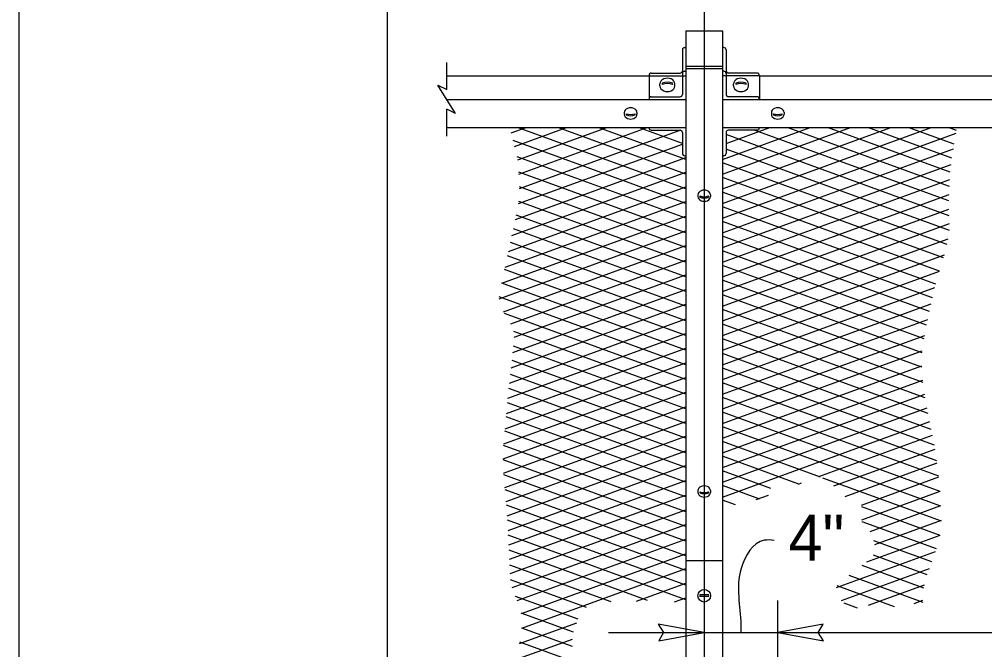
# Model space of a CAD drawing. Extents: x 0 to 2.83, y -0.03 to 1.83.
# Drawn here: x 0 to 0.2734, y 1.5079 to 1.6864 of the extents above; entities that cross this region are included whole.
import ezdxf

# ---------------------------------------------------------------- set-up
doc = ezdxf.new("R2010")
doc.units = 0
for name, color, linetype in [('52', 7, 'Continuous'), ('54', 7, 'Continuous'), ('55', 7, 'Continuous'), ('56', 7, 'Continuous'), ('57', 7, 'Continuous'), ('63', 7, 'Continuous')]:
    doc.layers.add(name, color=color, linetype=linetype)

msp = doc.modelspace()

# ---------------------------------------------------------------- linework, layer by layer
at = {"layer": '52'}
for p, q in [((0.18878094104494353, 1.6831667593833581), (0.19919760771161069, 1.6831667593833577)), ((0.18878094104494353, 1.6831667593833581), (0.18878094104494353, 1.6707794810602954)), ((0.1991976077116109, 1.6831667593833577), (0.19919760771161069, 1.6707794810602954)), ((0.18780437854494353, 1.6777778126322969), (0.18780437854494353, 1.665152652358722)), ((0.1884554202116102, 1.6784288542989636), (0.18878094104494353, 1.6784288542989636)), ((0.199523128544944, 1.6784288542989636), (0.19919760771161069, 1.6784288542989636)), ((0.20017417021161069, 1.6777778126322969), (0.20017417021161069, 1.665152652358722)), ((0.17901531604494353, 1.6711973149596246), (0.1871533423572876, 1.6711973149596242)), ((0.1884554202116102, 1.6717331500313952), (0.18878094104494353, 1.6717331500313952)), ((0.18878094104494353, 1.6731232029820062), (0.1991976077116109, 1.6731232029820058)), ((0.19919760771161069, 1.6723751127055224), (0.18878094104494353, 1.6723751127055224)), ((0.18878094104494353, 1.6707794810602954), (0.18878094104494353, 1.5329433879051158)), ((0.199523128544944, 1.6717331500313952), (0.19919760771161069, 1.6717331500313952)), ((0.19919760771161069, 1.6707794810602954), (0.19919760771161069, 1.5329433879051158)), ((0.20896323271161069, 1.6711973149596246), (0.20082520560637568, 1.6711973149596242)), ((0.1210726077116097, 1.670449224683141), (0.17836427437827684, 1.670449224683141)), ((0.17836427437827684, 1.670546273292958), (0.17836427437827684, 1.6637535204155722)), ((0.17836427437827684, 1.670449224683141), (0.18878094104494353, 1.670449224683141)), ((0.18145672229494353, 1.6675598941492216), (0.18145672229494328, 1.6681390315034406)), ((0.18568849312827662, 1.6675598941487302), (0.18568849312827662, 1.6681390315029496)), ((0.20961427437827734, 1.670449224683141), (0.19919760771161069, 1.670449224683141)), ((0.20229005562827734, 1.6675598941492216), (0.2022900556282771, 1.6681390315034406)), ((0.20652182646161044, 1.6675598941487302), (0.20652182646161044, 1.6681390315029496)), ((0.20961427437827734, 1.670546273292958), (0.20961427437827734, 1.6637535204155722)), ((0.2096142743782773, 1.670449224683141), (0.6054476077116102, 1.670449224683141)), ((0.1210726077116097, 1.6637535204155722), (0.18878094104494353, 1.6637535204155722)), ((0.17901531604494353, 1.6645016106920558), (0.18715333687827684, 1.6645016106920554)), ((0.1991976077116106, 1.6637535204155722), (0.6054476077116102, 1.6637535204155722)), ((0.20896323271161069, 1.6645016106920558), (0.20082521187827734, 1.6645016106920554)), ((0.17136557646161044, 1.6600087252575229), (0.1713655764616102, 1.659518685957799)), ((0.17494630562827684, 1.660008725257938), (0.17494630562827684, 1.6595186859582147)), ((0.21303224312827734, 1.660008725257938), (0.21303224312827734, 1.6595186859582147)), ((0.21661297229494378, 1.6600087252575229), (0.216612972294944, 1.659518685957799)), ((0.1210726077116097, 1.6557738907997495), (0.18878094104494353, 1.6557738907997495)), ((0.17836427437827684, 1.6557628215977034), (0.17836427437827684, 1.6556768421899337)), ((0.17901531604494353, 1.655025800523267), (0.18715333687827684, 1.655025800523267)), ((0.18780437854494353, 1.6543747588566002), (0.18780437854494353, 1.6484453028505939)), ((0.1991976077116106, 1.6557738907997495), (0.6054476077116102, 1.6557738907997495)), ((0.20017417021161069, 1.6543747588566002), (0.20017417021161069, 1.6484453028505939)), ((0.20896323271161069, 1.655025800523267), (0.20082521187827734, 1.655025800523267)), ((0.20961427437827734, 1.6557628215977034), (0.20961427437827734, 1.6556768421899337)), ((0.1884554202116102, 1.6477942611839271), (0.18878094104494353, 1.6477942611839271)), ((0.199523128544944, 1.6477942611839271), (0.19919760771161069, 1.6477942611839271)), ((0.19219890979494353, 1.636711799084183), (0.19219890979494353, 1.6362217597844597)), ((0.19577963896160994, 1.6367117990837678), (0.1957796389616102, 1.636221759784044)), ((0.19219890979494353, 1.552925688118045), (0.19219890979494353, 1.552435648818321)), ((0.19577963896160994, 1.5529256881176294), (0.1957796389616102, 1.552435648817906)), ((0.18878094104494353, 1.5330983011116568), (0.19919760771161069, 1.5330983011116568)), ((0.18878094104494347, 1.5329433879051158), (0.18878094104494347, 1.1621577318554)), ((0.1991976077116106, 1.5329433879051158), (0.1991976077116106, 1.1621577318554)), ((0.19523631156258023, 1.5233909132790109), (0.19274223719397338, 1.5233909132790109)), ((0.19523631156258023, 1.5229297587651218), (0.19274223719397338, 1.5229297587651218))]:
    msp.add_line(p, q, dxfattribs=at)
msp.add_circle((0.1939892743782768, 1.5231603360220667), 0.0017903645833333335, dxfattribs=at)
for centre, radius, start, end in [((0.1884554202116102, 1.6777778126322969), 0.0006510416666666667, 90, 180), ((0.199523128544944, 1.6777778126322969), 0.0006510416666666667, 7.0164775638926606e-15, 90), ((0.17901531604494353, 1.670546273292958), 0.0006510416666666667, 90.00000000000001, 188.57284229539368), ((0.18715333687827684, 1.6718483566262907), 0.0006510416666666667, 270, 0), ((0.1884554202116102, 1.6710821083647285), 0.0006510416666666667, 90, 180), ((0.199523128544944, 1.6710821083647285), 0.0006510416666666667, 7.0164775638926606e-15, 90), ((0.20082521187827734, 1.6718483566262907), 0.0006510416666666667, 180, 270), ((0.20896323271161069, 1.670546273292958), 0.0006510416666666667, 351.4271577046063, 90), ((0.18357260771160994, 1.6645999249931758), 0.004024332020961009, 68.51761783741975, 111.48238216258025), ((0.18357260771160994, 1.66418861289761), 0.004024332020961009, 68.51761783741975, 111.48238216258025), ((0.20440594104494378, 1.6645999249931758), 0.004024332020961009, 68.51761783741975, 111.48238216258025), ((0.20440594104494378, 1.66418861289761), 0.004024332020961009, 68.51761783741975, 111.48238216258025), ((0.17901531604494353, 1.663850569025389), 0.0006510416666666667, 90.00000000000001, 188.57284229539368), ((0.18715333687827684, 1.665152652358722), 0.0006510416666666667, 270, 0), ((0.20082521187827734, 1.665152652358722), 0.0006510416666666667, 180, 270), ((0.20896323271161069, 1.663850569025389), 0.0006510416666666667, 351.4271577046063, 90), ((0.17315594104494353, 1.66286134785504), 0.003405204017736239, 248.51761783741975, 291.4823821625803), ((0.17315594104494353, 1.6625133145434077), 0.003405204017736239, 248.51761783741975, 291.4823821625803), ((0.21482260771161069, 1.66286134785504), 0.003405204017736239, 248.51761783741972, 291.4823821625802), ((0.21482260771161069, 1.6625133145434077), 0.003405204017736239, 248.51761783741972, 291.4823821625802), ((0.17901531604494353, 1.6556768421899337), 0.0006510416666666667, 171.42715770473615, 270), ((0.18715333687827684, 1.6543747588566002), 0.0006510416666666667, 0, 89.99999999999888), ((0.20082521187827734, 1.6543747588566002), 0.0006510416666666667, 90.00000000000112, 180), ((0.20896323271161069, 1.6556768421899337), 0.0006510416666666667, 270, 8.572842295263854), ((0.1884554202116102, 1.6484453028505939), 0.0006510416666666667, 180, 270), ((0.199523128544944, 1.6484453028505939), 0.0006510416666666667, 270, 360), ((0.19398927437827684, 1.639564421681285), 0.003405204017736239, 248.51761783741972, 291.4823821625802), ((0.19398927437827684, 1.6392163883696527), 0.003405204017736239, 248.51761783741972, 291.4823821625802), ((0.19398927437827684, 1.5557783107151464), 0.003405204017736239, 248.51761783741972, 291.4823821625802), ((0.19398927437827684, 1.5554302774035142), 0.003405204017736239, 248.51761783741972, 291.4823821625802), ((0.1939892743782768, 1.5231603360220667), 0.0012681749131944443, 169.52431830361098, 190.47568169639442), ((0.1939892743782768, 1.5231603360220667), 0.0012681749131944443, 349.5243183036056, 10.475681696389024)]:
    msp.add_arc(centre, radius, start, end, dxfattribs=at)
for centre, major_axis, ratio, start_param, end_param in [((0.18357260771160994, 1.6681390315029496), (0.002115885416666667, 0), 0.7546999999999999, 0, 3.141592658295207), ((0.18357260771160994, 1.6681390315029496), (0.001498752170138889, 0), 0.7547, 2.9587575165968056, 3.3244277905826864), ((0.18357260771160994, 1.6681390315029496), (0.001498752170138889, 0), 0.7547, 6.100350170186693, 6.466020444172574), ((0.20440594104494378, 1.6681390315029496), (0.002115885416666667, 0), 0.7546999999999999, 0, 3.141592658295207), ((0.20440594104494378, 1.6681390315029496), (0.001498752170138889, 0), 0.7547, 2.9587575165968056, 3.3244277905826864), ((0.20440594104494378, 1.6681390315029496), (0.001498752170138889, 0), 0.7547, 6.100350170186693, 6.466020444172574), ((0.18357260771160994, 1.6675598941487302), (0.002115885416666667, 0), 0.7546999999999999, 3.141592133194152, 6.283185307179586), ((0.20440594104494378, 1.6675598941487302), (0.002115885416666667, 0), 0.7546999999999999, 3.141592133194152, 6.283185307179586), ((0.17315594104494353, 1.660008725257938), (0.0017903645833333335, 0), 0.7546999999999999, 0, 3.1415931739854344), ((0.21482260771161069, 1.660008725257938), (-0.0017903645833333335, 2.1925642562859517e-19), 0.7546999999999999, 3.141592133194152, 6.283185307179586), ((0.17315594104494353, 1.6595186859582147), (0.0017903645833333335, 0), 0.7546999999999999, 3.141590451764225, 6.283185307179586), ((0.17315594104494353, 1.6595186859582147), (0.0012681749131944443, 0), 0.7547000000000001, 2.9587575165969, 3.3244277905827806), ((0.17315594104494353, 1.6595186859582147), (0.0012681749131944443, 0), 0.7547000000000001, 6.100350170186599, 6.46602044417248), ((0.21482260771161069, 1.6595186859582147), (-0.0017903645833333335, 2.1925642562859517e-19), 0.7546999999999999, 1.6226399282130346e-16, 3.141594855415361), ((0.21482260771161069, 1.6595186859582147), (-0.0012681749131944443, 1.5530663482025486e-19), 0.7547000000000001, 6.100350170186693, 6.466020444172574), ((0.21482260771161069, 1.6595186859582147), (-0.0012681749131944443, 1.5530663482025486e-19), 0.7547000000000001, 2.9587575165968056, 3.3244277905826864), ((0.19398927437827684, 1.636711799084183), (-0.0017903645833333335, 2.1925642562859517e-19), 0.7546999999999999, 3.141592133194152, 6.283185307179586), ((0.19398927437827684, 1.6362217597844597), (-0.0017903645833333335, 2.1925642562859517e-19), 0.7546999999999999, 1.6226399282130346e-16, 3.141594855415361), ((0.19398927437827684, 1.6362217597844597), (-0.0012681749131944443, 1.5530663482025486e-19), 0.7547000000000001, 6.100350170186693, 6.466020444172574), ((0.19398927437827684, 1.6362217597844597), (-0.0012681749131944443, 1.5530663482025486e-19), 0.7547000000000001, 2.9587575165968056, 3.3244277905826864), ((0.19398927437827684, 1.552925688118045), (-0.0017903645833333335, 2.1925642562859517e-19), 0.7546999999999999, 3.141592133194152, 6.283185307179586), ((0.19398927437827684, 1.552435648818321), (-0.0017903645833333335, 2.1925642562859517e-19), 0.7546999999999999, 1.6226399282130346e-16, 3.141594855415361), ((0.19398927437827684, 1.552435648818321), (-0.0012681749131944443, 1.5530663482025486e-19), 0.7547000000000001, 6.100350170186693, 6.466020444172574), ((0.19398927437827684, 1.552435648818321), (-0.0012681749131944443, 1.5530663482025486e-19), 0.7547000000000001, 2.9587575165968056, 3.3244277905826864)]:
    msp.add_ellipse(centre, major_axis=major_axis, ratio=ratio, start_param=start_param, end_param=end_param, dxfattribs=at)
at = {"layer": '54'}
for points in [[(0.1939892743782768, 1.5127436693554), (0.18099760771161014, 1.5151186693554), (0.18250594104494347, 1.5127436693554), (0.18114760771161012, 1.5103436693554)], [(0.2148226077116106, 1.5127436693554), (0.22781427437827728, 1.5103686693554), (0.22630594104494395, 1.5127436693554), (0.22766427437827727, 1.5151436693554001)]]:
    msp.add_lwpolyline(points, close=True, dxfattribs=at)
at = {"layer": '55'}
for p, q in [((0.12107260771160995, 1.6665491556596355), (0.12107260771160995, 1.6741924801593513)), ((0.12358726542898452, 1.659698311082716), (0.11855794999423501, 1.6678087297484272)), ((0.11855794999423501, 1.6678087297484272), (0.12107260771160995, 1.6665491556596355)), ((0.12358726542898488, 1.6596983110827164), (0.12107260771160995, 1.6609578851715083)), ((0.12107260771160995, 1.6533145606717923), (0.12107260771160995, 1.6609578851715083)), ((0.13932071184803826, 1.6542347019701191), (0.14354959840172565, 1.6557738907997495)), ((0.14029528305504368, 1.6504324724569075), (0.15497070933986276, 1.6557738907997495)), ((0.18878094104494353, 1.6384194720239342), (0.14110006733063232, 1.6557738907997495)), ((0.14115966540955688, 1.6465901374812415), (0.1663918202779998, 1.6557738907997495)), ((0.1415175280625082, 1.642563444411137), (0.17781293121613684, 1.6557738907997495)), ((0.14170345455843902, 1.6384741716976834), (0.18717368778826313, 1.6550239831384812)), ((0.18878094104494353, 1.6425764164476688), (0.1525211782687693, 1.6557738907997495)), ((0.18878094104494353, 1.6467333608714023), (0.16394228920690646, 1.6557738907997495)), ((0.18780437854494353, 1.651245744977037), (0.1753634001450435, 1.6557738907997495)), ((0.19919760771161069, 1.6467306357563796), (0.2240437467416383, 1.6557738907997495)), ((0.19919760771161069, 1.6425736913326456), (0.2354648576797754, 1.6557738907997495)), ((0.19919760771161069, 1.6384167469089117), (0.24688596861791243, 1.6557738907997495)), ((0.19919760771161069, 1.6342598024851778), (0.2583070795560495, 1.6557738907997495)), ((0.20017417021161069, 1.6512430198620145), (0.2126226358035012, 1.6557738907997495)), ((0.2632446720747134, 1.6349742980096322), (0.20815362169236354, 1.655025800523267)), ((0.2634595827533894, 1.639053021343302), (0.2175193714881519, 1.6557738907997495)), ((0.26370339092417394, 1.64312122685), (0.228940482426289, 1.6557738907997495)), ((0.2641356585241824, 1.6471208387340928), (0.2403615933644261, 1.6557738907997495)), ((0.2648088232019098, 1.651032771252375), (0.2517827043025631, 1.6557738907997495)), ((0.2654981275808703, 1.654938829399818), (0.2632038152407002, 1.6557738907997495)), ((0.18878094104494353, 1.6342625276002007), (0.13984055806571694, 1.6520753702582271)), ((0.19919760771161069, 1.6301028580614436), (0.2653652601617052, 1.654185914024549)), ((0.26337624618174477, 1.6307694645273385), (0.20017417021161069, 1.6537731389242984)), ((0.1414147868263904, 1.6342121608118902), (0.18780437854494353, 1.6510965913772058)), ((0.19919760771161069, 1.6259459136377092), (0.2645813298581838, 1.6497436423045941)), ((0.2634268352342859, 1.6265941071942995), (0.20017417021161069, 1.649616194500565)), ((0.14050845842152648, 1.629725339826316), (0.18878094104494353, 1.6472950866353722)), ((0.18878094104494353, 1.6301055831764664), (0.14101239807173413, 1.6474919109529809)), ((0.26280864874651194, 1.6226621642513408), (0.19919760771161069, 1.6458146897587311)), ((0.19919760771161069, 1.6217889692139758), (0.26391011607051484, 1.6453423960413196)), ((0.13953109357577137, 1.6252126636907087), (0.18878094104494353, 1.6431381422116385)), ((0.18878094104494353, 1.6259486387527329), (0.14147072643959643, 1.643168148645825)), ((0.2618136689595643, 1.6188673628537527), (0.19919760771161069, 1.6416577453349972)), ((0.19919760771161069, 1.6176320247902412), (0.26356668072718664, 1.641060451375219)), ((0.13854712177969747, 1.6206975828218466), (0.18878094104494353, 1.638981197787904)), ((0.18878094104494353, 1.6217916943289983), (0.14169891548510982, 1.638928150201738)), ((0.2606688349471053, 1.6151271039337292), (0.19919760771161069, 1.6375008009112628)), ((0.19919760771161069, 1.6134750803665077), (0.2633447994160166, 1.636822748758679)), ((0.13759752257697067, 1.616195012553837), (0.18878094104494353, 1.6348242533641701)), ((0.18878094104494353, 1.617634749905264), (0.14149675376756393, 1.6348447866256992)), ((0.25956432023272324, 1.611372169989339), (0.19919760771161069, 1.6333438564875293)), ((0.19919760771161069, 1.6093181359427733), (0.26327682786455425, 1.6326410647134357)), ((0.13668731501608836, 1.611706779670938), (0.18878094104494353, 1.630667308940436)), ((0.18878094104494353, 1.6134778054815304), (0.14076772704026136, 1.6309531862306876)), ((0.18878094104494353, 1.6093208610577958), (0.13994238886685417, 1.6270966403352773)), ((0.2586490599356, 1.6075483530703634), (0.19919760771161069, 1.6291869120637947)), ((0.19919760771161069, 1.6051611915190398), (0.2634669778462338, 1.6285533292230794)), ((0.13590588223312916, 1.607265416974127), (0.18878094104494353, 1.626510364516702)), ((0.2577933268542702, 1.6037028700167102), (0.19919760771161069, 1.6250299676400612)), ((0.19919760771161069, 1.6010042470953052), (0.2631311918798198, 1.6242741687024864)), ((0.13711901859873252, 1.603550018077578), (0.18878094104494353, 1.6223534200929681)), ((0.18878094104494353, 1.6051639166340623), (0.13910071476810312, 1.6232460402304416)), ((0.18878094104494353, 1.6010069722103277), (0.13826780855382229, 1.6193922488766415)), ((0.25699132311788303, 1.5998378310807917), (0.19919760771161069, 1.6208730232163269)), ((0.19919760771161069, 1.5968473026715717), (0.26206119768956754, 1.6197277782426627)), ((0.13918175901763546, 1.6001438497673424), (0.18878094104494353, 1.6181964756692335)), ((0.2562783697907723, 1.5959403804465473), (0.19919760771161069, 1.6167160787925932)), ((0.18878094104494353, 1.5968500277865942), (0.13745984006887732, 1.6155293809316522)), ((0.14017977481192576, 1.5963501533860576), (0.18878094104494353, 1.6140395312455)), ((0.19919760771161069, 1.5926903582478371), (0.260646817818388, 1.6150560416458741)), ((0.18878094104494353, 1.5926930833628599), (0.13667750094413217, 1.6116571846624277)), ((0.2557243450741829, 1.5919850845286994), (0.19919760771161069, 1.6125591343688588)), ((0.13978525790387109, 1.592049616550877), (0.18878094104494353, 1.6098825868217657)), ((0.19919760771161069, 1.5885334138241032), (0.259314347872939, 1.6104141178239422)), ((0.25563382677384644, 1.5878610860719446), (0.19919760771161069, 1.6084021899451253)), ((0.18878094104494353, 1.5885361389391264), (0.1359366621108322, 1.6077698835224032)), ((0.13933341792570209, 1.587728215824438), (0.18878094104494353, 1.6057256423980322)), ((0.19919760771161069, 1.5843764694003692), (0.2582725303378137, 1.6058779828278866)), ((0.18878094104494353, 1.5843791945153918), (0.13739453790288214, 1.6030823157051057)), ((0.2559803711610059, 1.583578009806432), (0.19919760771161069, 1.6042452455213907)), ((0.13886441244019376, 1.5834005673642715), (0.18878094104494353, 1.6015686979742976)), ((0.19919760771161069, 1.5802195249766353), (0.25729936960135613, 1.601366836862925)), ((0.25661634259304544, 1.5791895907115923), (0.19919760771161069, 1.6000883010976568)), ((0.13841791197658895, 1.5790811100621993), (0.18878094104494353, 1.5974117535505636)), ((0.18878094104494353, 1.5802222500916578), (0.14006127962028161, 1.5979547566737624)), ((0.19919760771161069, 1.5760625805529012), (0.25644274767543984, 1.5968981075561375)), ((0.25742395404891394, 1.5747386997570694), (0.19919760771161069, 1.5959313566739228)), ((0.1380319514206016, 1.574783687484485), (0.18878094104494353, 1.5932548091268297)), ((0.18878094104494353, 1.576065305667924), (0.13995773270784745, 1.593835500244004)), ((0.19919760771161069, 1.5719056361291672), (0.25577526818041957, 1.5924982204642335)), ((0.25831074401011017, 1.5702589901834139), (0.19919760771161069, 1.591774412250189)), ((0.13760777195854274, 1.5704723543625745), (0.18878094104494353, 1.5890978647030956)), ((0.18878094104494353, 1.5719083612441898), (0.13955687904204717, 1.5898244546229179)), ((0.19919760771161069, 1.5677486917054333), (0.25562027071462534, 1.5882848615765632)), ((0.259176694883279, 1.5657868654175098), (0.19919760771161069, 1.5876174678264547)), ((0.1372144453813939, 1.5661722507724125), (0.18878094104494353, 1.5849409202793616)), ((0.18878094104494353, 1.5677514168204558), (0.139126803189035, 1.5858240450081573)), ((0.19919760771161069, 1.5635917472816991), (0.25590602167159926, 1.584231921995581)), ((0.2599238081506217, 1.5613579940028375), (0.19919760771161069, 1.5834605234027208)), ((0.13702930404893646, 1.5619479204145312), (0.18878094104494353, 1.5807839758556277)), ((0.18878094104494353, 1.563594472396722), (0.1386969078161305, 1.5818235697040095)), ((0.18878094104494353, 1.559437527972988), (0.13829644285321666, 1.5778123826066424)), ((0.19919760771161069, 1.5594348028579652), (0.25644164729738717, 1.5802699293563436)), ((0.2604703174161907, 1.5570021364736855), (0.19919760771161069, 1.5793035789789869)), ((0.1371738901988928, 1.5578436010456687), (0.18878094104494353, 1.5766270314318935)), ((0.19919760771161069, 1.5552778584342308), (0.25711690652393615, 1.5763587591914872)), ((0.26082288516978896, 1.5527168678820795), (0.19919760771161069, 1.5751466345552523)), ((0.13754063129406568, 1.55382013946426), (0.18878094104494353, 1.5724700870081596)), ((0.18878094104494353, 1.5552805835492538), (0.13793934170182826, 1.573785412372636)), ((0.19919760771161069, 1.5511209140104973), (0.25786853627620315, 1.5724753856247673)), ((0.18878094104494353, 1.5511236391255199), (0.1375373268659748, 1.5697747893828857)), ((0.26103983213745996, 1.548480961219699), (0.19919760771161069, 1.5709896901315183)), ((0.13793995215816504, 1.549808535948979), (0.18878094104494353, 1.5683131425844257)), ((0.22691813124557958, 1.5567433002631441), (0.19919760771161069, 1.5668327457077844)), ((0.2264476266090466, 1.5568821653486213), (0.2586395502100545, 1.5685990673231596)), ((0.18878094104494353, 1.5469666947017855), (0.13718356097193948, 1.5657466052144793)), ((0.13822352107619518, 1.5457548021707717), (0.18878094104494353, 1.564156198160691)), ((0.23071935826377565, 1.554280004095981), (0.2593721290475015, 1.5647087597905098)), ((0.18878094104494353, 1.5428097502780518), (0.13702864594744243, 1.5616460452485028)), ((0.22084326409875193, 1.5547974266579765), (0.19919760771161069, 1.5626758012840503)), ((0.13844172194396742, 1.5416772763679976), (0.18878094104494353, 1.5599992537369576)), ((0.23387496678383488, 1.5512716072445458), (0.2600090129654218, 1.5607836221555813)), ((0.18878094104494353, 1.5386528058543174), (0.13720468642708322, 1.5574250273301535)), ((0.21284412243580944, 1.5535519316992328), (0.19919760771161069, 1.5585188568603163)), ((0.26117288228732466, 1.5442755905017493), (0.22760595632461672, 1.556492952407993)), ((0.2385701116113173, 1.5488235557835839), (0.26049067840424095, 1.5568019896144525)), ((0.13863387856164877, 1.5375902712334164), (0.18878094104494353, 1.5558423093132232)), ((0.20972518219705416, 1.5505301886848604), (0.19919760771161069, 1.5543619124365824)), ((0.2206644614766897, 1.554777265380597), (0.22154742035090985, 1.5550986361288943)), ((0.18878094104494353, 1.534495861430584), (0.13761322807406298, 1.5531193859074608)), ((0.13882639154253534, 1.5335033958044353), (0.18878094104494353, 1.5516853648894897)), ((0.20869043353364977, 1.5504190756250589), (0.21217169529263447, 1.5516861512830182)), ((0.2385977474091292, 1.5446766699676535), (0.26081971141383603, 1.5527648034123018)), ((0.18878094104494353, 1.5303389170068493), (0.13802454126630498, 1.54881273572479)), ((0.20287278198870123, 1.5488673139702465), (0.19919760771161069, 1.5502049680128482)), ((0.26081190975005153, 1.5402500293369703), (0.23863728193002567, 1.5483209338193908)), ((0.2409972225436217, 1.5413930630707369), (0.26103163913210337, 1.5486849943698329)), ((0.13904626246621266, 1.5294264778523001), (0.18878094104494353, 1.5475284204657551)), ((0.18878094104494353, 1.5261819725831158), (0.13829193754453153, 1.5445584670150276)), ((0.13961874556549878, 1.5254779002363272), (0.18878094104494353, 1.5433714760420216)), ((0.2597930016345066, 1.536463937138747), (0.23876156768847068, 1.5441187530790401)), ((0.24228223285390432, 1.5377038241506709), (0.2611651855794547, 1.544576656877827)), ((0.18878094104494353, 1.5220250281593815), (0.1385070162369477, 1.540323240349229)), ((0.2400557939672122, 1.5327365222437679), (0.26082125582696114, 1.540294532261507)), ((0.14099514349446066, 1.521821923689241), (0.18878094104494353, 1.5392145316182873)), ((0.258486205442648, 1.5327826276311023), (0.24207926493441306, 1.5387542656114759)), ((0.17794456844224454, 1.5218122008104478), (0.13870281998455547, 1.5360950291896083)), ((0.1421995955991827, 1.518103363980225), (0.18878094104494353, 1.5350575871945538)), ((0.2314600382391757, 1.5254509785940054), (0.2595236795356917, 1.535665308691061)), ((0.2571869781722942, 1.5290985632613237), (0.24198123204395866, 1.5346330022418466)), ((0.16766222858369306, 1.5213977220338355), (0.1389101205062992, 1.5318626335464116)), ((0.256196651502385, 1.5253020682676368), (0.2386893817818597, 1.5316741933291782)), ((0.14237643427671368, 1.5140107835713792), (0.18878094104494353, 1.5309006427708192)), ((0.23292098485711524, 1.5218257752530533), (0.25779244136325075, 1.5308782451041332)), ((0.2559904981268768, 1.5212201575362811), (0.2350277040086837, 1.5288499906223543)), ((0.16064675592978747, 1.5197942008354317), (0.13915960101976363, 1.5276148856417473)), ((0.17477437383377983, 1.5216457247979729), (0.18878094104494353, 1.5267436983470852)), ((0.24792806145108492, 1.5199977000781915), (0.23163068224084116, 1.5259294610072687)), ((0.24056643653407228, 1.5204515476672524), (0.2563854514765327, 1.52620919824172)), ((0.15832842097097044, 1.5164810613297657), (0.14053297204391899, 1.5229580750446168)), ((0.18557287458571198, 1.521419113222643), (0.18878094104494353, 1.522586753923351)), ((0.2148226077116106, 1.4624507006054), (0.2148226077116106, 1.5217898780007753)), ((0.23741177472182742, 1.519668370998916), (0.2336374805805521, 1.5210421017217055)), ((0.25343289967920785, 1.5209776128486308), (0.2559203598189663, 1.5218829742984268)), ((0.15698466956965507, 1.512813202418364), (0.14217955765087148, 1.518201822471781)), ((0.14164352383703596, 1.5095870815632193), (0.15787079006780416, 1.515493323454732)), ((0.15672054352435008, 1.508752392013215), (0.14237379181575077, 1.513974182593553)), ((0.16687301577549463, 1.5127436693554), (0.1939892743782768, 1.5127436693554)), ((0.1939892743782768, 1.5127436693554), (0.2148226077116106, 1.5127436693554)), ((0.2148226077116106, 1.5127436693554), (0.5898226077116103, 1.5127436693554)), ((0.1403532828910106, 1.5049605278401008), (0.15664321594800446, 1.5108895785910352)), ((0.18878094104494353, 1.4929264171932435), (0.14174813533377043, 1.510044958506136))]:
    msp.add_line(p, q, dxfattribs=at)
msp.add_spline([(0.21382132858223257, 1.5388461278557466), (0.2110112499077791, 1.5388640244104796), (0.20445631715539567, 1.530900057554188), (0.2043853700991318, 1.515007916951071), (0.2044059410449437, 1.5127436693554)], degree=3, dxfattribs=at)
at = {"layer": '56'}
msp.add_line((0.1939892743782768, 1.7266594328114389), (0.1939892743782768, 1.0713374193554), dxfattribs=at)
at = {"layer": '63'}
msp.add_line((0, 0), (0, 1.8333333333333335), dxfattribs=at)
msp.add_lwpolyline([(2.729175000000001, 1.770775), (0.10417500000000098, 1.770775), (0.10417500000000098, 0.06244166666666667), (2.729175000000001, 0.06244166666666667)], close=True, dxfattribs=at)

# ---------------------------------------------------------------- texts
at = {"layer": '57'}
msp.add_text('4"', height=0.012980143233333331, dxfattribs=at).set_placement((0.21785565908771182, 1.5330992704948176))

doc.saveas('drawing.dxf')
